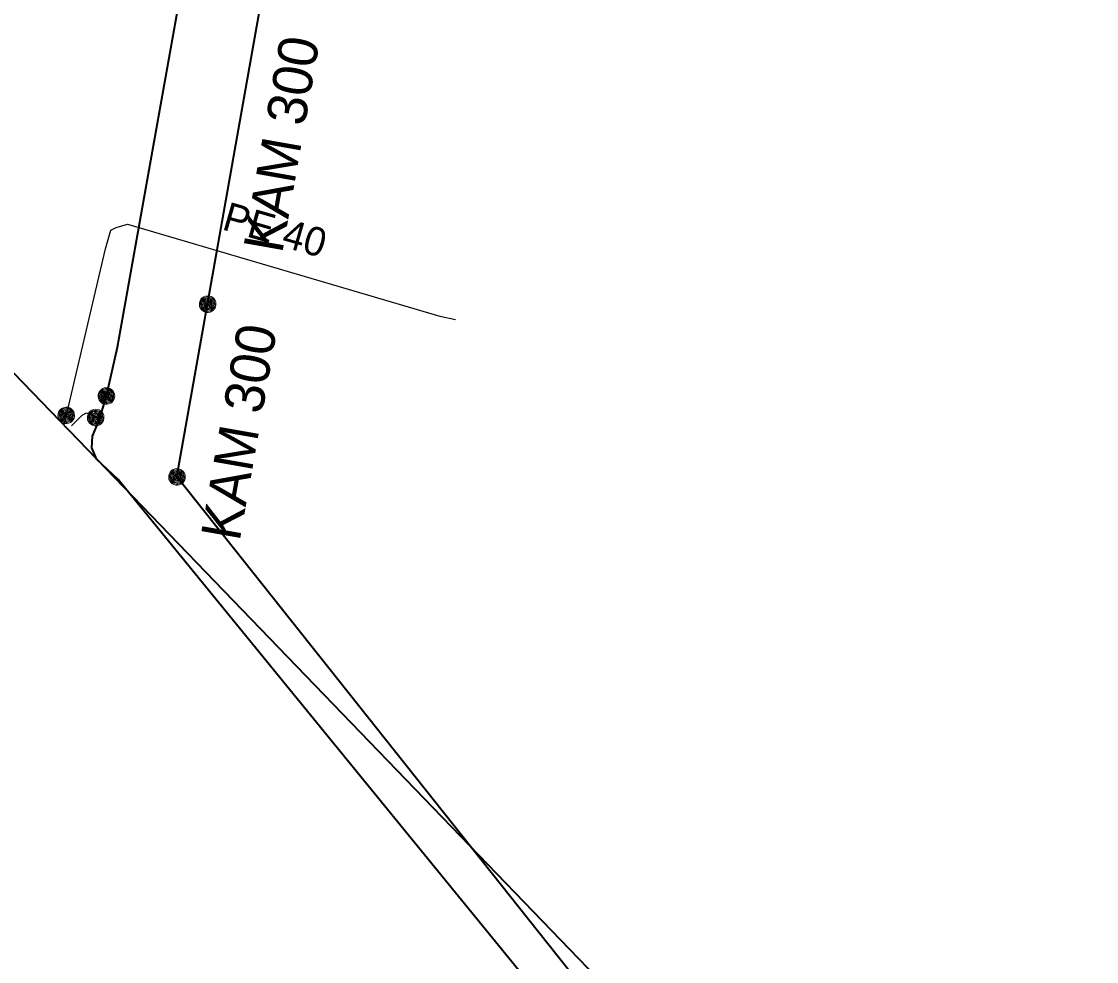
# Model space of a CAD drawing. Extents: x -867121 to -866743, y -1014362 to -1014088.
# Drawn here: x -866794.67 to -866764.7, y -1014270.01 to -1014243.81 of the extents above; entities that cross this region are included whole.
import ezdxf

# ---------------------------------------------------------------- set-up
doc = ezdxf.new("R2010")
doc.units = 0
doc.header["$LTSCALE"] = 0.44
for name, color, linetype, lineweight in [('1', 7, 'Continuous', 35), ('12', 7, 'Continuous', 13), ('21', 7, 'Continuous', 35), ('3', 7, 'Continuous', 25), ('32', 7, 'Continuous', 13)]:
    doc.layers.add(name, color=color, linetype=linetype, lineweight=lineweight)

msp = doc.modelspace()

# ---------------------------------------------------------------- linework, layer by layer
at = {"layer": '1'}
for p, q in [((-866764.699, -1014284.885), (-866792.574, -1014256.008)), ((-866765.275, -1014289.274), (-866791.98, -1014256.58))]:
    msp.add_line(p, q, dxfattribs=at)
for points in [[(-866791.979, -1014256.58), (-866792.57, -1014256.02), (-866792.709, -1014255.69), (-866792.69, -1014255.37), (-866792.5, -1014254.9), (-866792.3, -1014254.24), (-866792, -1014252.89), (-866783.03, -1014202.67), (-866778.1, -1014171.95), (-866772.02, -1014133.72), (-866768.851, -1014115.7)], [(-866792.574, -1014256.008), (-866841.087, -1014205.753), (-866857.467, -1014153.141), (-866859.393, -1014135.973), (-866869.502, -1014132.716), (-866897.758, -1014124.346), (-866897.929, -1014124.295)]]:
    msp.add_lwpolyline(points, dxfattribs=at)
at = {"layer": '12'}
for points in [[(-866792.076, -1014254.249), (-866792.082, -1014254.197), (-866792.099, -1014254.147), (-866792.128, -1014254.103), (-866792.165, -1014254.066), (-866792.21, -1014254.039), (-866792.26, -1014254.022), (-866792.313, -1014254.018), (-866792.365, -1014254.025), (-866792.414, -1014254.044), (-866792.457, -1014254.073), (-866792.493, -1014254.112), (-866792.519, -1014254.157), (-866792.535, -1014254.208), (-866792.538, -1014254.26), (-866792.53, -1014254.312), (-866792.51, -1014254.361), (-866792.479, -1014254.404), (-866792.44, -1014254.438), (-866792.394, -1014254.464), (-866792.343, -1014254.478), (-866792.29, -1014254.48), (-866792.239, -1014254.47), (-866792.191, -1014254.449), (-866792.148, -1014254.418), (-866792.114, -1014254.377), (-866792.09, -1014254.331), (-866792.078, -1014254.28)], [(-866792.106, -1014254.249), (-866792.112, -1014254.2), (-866792.129, -1014254.154), (-866792.157, -1014254.114), (-866792.194, -1014254.082), (-866792.238, -1014254.06), (-866792.286, -1014254.049), (-866792.335, -1014254.049), (-866792.382, -1014254.062), (-866792.425, -1014254.086), (-866792.461, -1014254.119), (-866792.488, -1014254.16), (-866792.504, -1014254.207), (-866792.508, -1014254.256), (-866792.501, -1014254.304), (-866792.482, -1014254.349), (-866792.452, -1014254.389), (-866792.414, -1014254.42), (-866792.37, -1014254.44), (-866792.322, -1014254.45), (-866792.273, -1014254.448), (-866792.226, -1014254.433), (-866792.183, -1014254.408), (-866792.149, -1014254.374), (-866792.123, -1014254.332), (-866792.109, -1014254.285)], [(-866792.136, -1014254.249), (-866792.142, -1014254.204), (-866792.159, -1014254.162), (-866792.187, -1014254.127), (-866792.223, -1014254.1), (-866792.265, -1014254.083), (-866792.31, -1014254.078), (-866792.355, -1014254.084), (-866792.396, -1014254.103), (-866792.431, -1014254.131), (-866792.458, -1014254.168), (-866792.474, -1014254.21), (-866792.478, -1014254.255), (-866792.471, -1014254.3), (-866792.452, -1014254.341), (-866792.423, -1014254.375), (-866792.386, -1014254.401), (-866792.343, -1014254.417), (-866792.298, -1014254.42), (-866792.253, -1014254.412), (-866792.213, -1014254.392), (-866792.179, -1014254.363), (-866792.153, -1014254.325), (-866792.139, -1014254.282)], [(-866792.166, -1014254.249), (-866792.171, -1014254.208), (-866792.189, -1014254.171), (-866792.216, -1014254.14), (-866792.251, -1014254.119), (-866792.291, -1014254.108), (-866792.332, -1014254.11), (-866792.371, -1014254.123), (-866792.405, -1014254.147), (-866792.43, -1014254.179), (-866792.445, -1014254.217), (-866792.448, -1014254.258), (-866792.44, -1014254.298), (-866792.42, -1014254.334), (-866792.391, -1014254.363), (-866792.354, -1014254.382), (-866792.314, -1014254.39), (-866792.273, -1014254.386), (-866792.235, -1014254.371), (-866792.203, -1014254.345), (-866792.18, -1014254.311), (-866792.167, -1014254.272)], [(-866792.196, -1014254.249), (-866792.201, -1014254.213), (-866792.219, -1014254.181), (-866792.245, -1014254.156), (-866792.279, -1014254.141), (-866792.315, -1014254.138), (-866792.35, -1014254.146), (-866792.381, -1014254.166), (-866792.404, -1014254.194), (-866792.417, -1014254.228), (-866792.417, -1014254.265), (-866792.406, -1014254.3), (-866792.385, -1014254.329), (-866792.355, -1014254.35), (-866792.32, -1014254.36), (-866792.283, -1014254.358), (-866792.249, -1014254.344), (-866792.222, -1014254.321), (-866792.203, -1014254.289), (-866792.196, -1014254.254)], [(-866792.226, -1014254.249), (-866792.231, -1014254.218), (-866792.248, -1014254.192), (-866792.274, -1014254.175), (-866792.304, -1014254.168), (-866792.335, -1014254.172), (-866792.362, -1014254.189), (-866792.38, -1014254.213), (-866792.388, -1014254.244), (-866792.384, -1014254.274), (-866792.369, -1014254.302), (-866792.345, -1014254.321), (-866792.315, -1014254.33), (-866792.284, -1014254.327), (-866792.256, -1014254.313), (-866792.236, -1014254.289), (-866792.226, -1014254.26)], [(-866792.256, -1014254.249), (-866792.261, -1014254.225), (-866792.278, -1014254.207), (-866792.301, -1014254.198), (-866792.325, -1014254.201), (-866792.346, -1014254.215), (-866792.357, -1014254.237), (-866792.357, -1014254.262), (-866792.345, -1014254.283), (-866792.325, -1014254.297), (-866792.3, -1014254.3), (-866792.277, -1014254.291), (-866792.261, -1014254.273)], [(-866792.286, -1014254.249), (-866792.291, -1014254.234), (-866792.306, -1014254.228), (-866792.321, -1014254.232), (-866792.328, -1014254.246), (-866792.324, -1014254.261), (-866792.311, -1014254.27), (-866792.296, -1014254.267), (-866792.286, -1014254.255)], [(-866793.196, -1014254.789), (-866793.202, -1014254.737), (-866793.219, -1014254.687), (-866793.248, -1014254.643), (-866793.285, -1014254.606), (-866793.33, -1014254.579), (-866793.38, -1014254.562), (-866793.433, -1014254.558), (-866793.485, -1014254.565), (-866793.534, -1014254.584), (-866793.577, -1014254.613), (-866793.613, -1014254.652), (-866793.639, -1014254.697), (-866793.655, -1014254.748), (-866793.658, -1014254.8), (-866793.65, -1014254.852), (-866793.63, -1014254.901), (-866793.599, -1014254.944), (-866793.56, -1014254.978), (-866793.514, -1014255.004), (-866793.463, -1014255.018), (-866793.41, -1014255.02), (-866793.359, -1014255.01), (-866793.311, -1014254.989), (-866793.268, -1014254.958), (-866793.234, -1014254.917), (-866793.21, -1014254.871), (-866793.198, -1014254.82)], [(-866793.226, -1014254.789), (-866793.232, -1014254.74), (-866793.249, -1014254.694), (-866793.277, -1014254.654), (-866793.314, -1014254.622), (-866793.358, -1014254.6), (-866793.406, -1014254.589), (-866793.455, -1014254.589), (-866793.502, -1014254.602), (-866793.545, -1014254.626), (-866793.581, -1014254.659), (-866793.608, -1014254.7), (-866793.624, -1014254.747), (-866793.628, -1014254.796), (-866793.621, -1014254.844), (-866793.602, -1014254.889), (-866793.572, -1014254.929), (-866793.534, -1014254.96), (-866793.49, -1014254.98), (-866793.442, -1014254.99), (-866793.393, -1014254.988), (-866793.346, -1014254.973), (-866793.303, -1014254.948), (-866793.269, -1014254.914), (-866793.243, -1014254.872), (-866793.229, -1014254.825)], [(-866793.256, -1014254.789), (-866793.262, -1014254.744), (-866793.279, -1014254.702), (-866793.307, -1014254.667), (-866793.343, -1014254.64), (-866793.385, -1014254.623), (-866793.43, -1014254.618), (-866793.475, -1014254.624), (-866793.516, -1014254.643), (-866793.551, -1014254.671), (-866793.578, -1014254.708), (-866793.594, -1014254.75), (-866793.598, -1014254.795), (-866793.591, -1014254.84), (-866793.572, -1014254.881), (-866793.543, -1014254.915), (-866793.506, -1014254.941), (-866793.463, -1014254.957), (-866793.418, -1014254.96), (-866793.373, -1014254.952), (-866793.333, -1014254.932), (-866793.299, -1014254.903), (-866793.273, -1014254.865), (-866793.259, -1014254.822)], [(-866793.286, -1014254.789), (-866793.291, -1014254.748), (-866793.309, -1014254.711), (-866793.336, -1014254.68), (-866793.371, -1014254.659), (-866793.411, -1014254.648), (-866793.452, -1014254.65), (-866793.491, -1014254.663), (-866793.525, -1014254.687), (-866793.55, -1014254.719), (-866793.565, -1014254.757), (-866793.568, -1014254.798), (-866793.56, -1014254.838), (-866793.54, -1014254.874), (-866793.511, -1014254.903), (-866793.474, -1014254.922), (-866793.434, -1014254.93), (-866793.393, -1014254.926), (-866793.355, -1014254.911), (-866793.323, -1014254.885), (-866793.3, -1014254.851), (-866793.287, -1014254.812)], [(-866792.375, -1014254.849), (-866792.382, -1014254.797), (-866792.399, -1014254.747), (-866792.428, -1014254.703), (-866792.465, -1014254.666), (-866792.51, -1014254.639), (-866792.559, -1014254.622), (-866792.613, -1014254.618), (-866792.664, -1014254.625), (-866792.713, -1014254.644), (-866792.757, -1014254.673), (-866792.793, -1014254.712), (-866792.819, -1014254.757), (-866792.835, -1014254.808), (-866792.838, -1014254.86), (-866792.83, -1014254.912), (-866792.809, -1014254.961), (-866792.779, -1014255.004), (-866792.74, -1014255.038), (-866792.694, -1014255.064), (-866792.642, -1014255.078), (-866792.59, -1014255.08), (-866792.539, -1014255.07), (-866792.49, -1014255.049), (-866792.448, -1014255.018), (-866792.414, -1014254.977), (-866792.39, -1014254.931), (-866792.377, -1014254.88)], [(-866792.406, -1014254.849), (-866792.412, -1014254.8), (-866792.429, -1014254.754), (-866792.456, -1014254.714), (-866792.494, -1014254.682), (-866792.538, -1014254.66), (-866792.586, -1014254.649), (-866792.635, -1014254.649), (-866792.681, -1014254.662), (-866792.725, -1014254.686), (-866792.761, -1014254.719), (-866792.788, -1014254.76), (-866792.804, -1014254.807), (-866792.808, -1014254.856), (-866792.801, -1014254.904), (-866792.782, -1014254.949), (-866792.752, -1014254.989), (-866792.713, -1014255.02), (-866792.669, -1014255.04), (-866792.622, -1014255.05), (-866792.573, -1014255.048), (-866792.526, -1014255.033), (-866792.483, -1014255.008), (-866792.448, -1014254.974), (-866792.423, -1014254.932), (-866792.409, -1014254.885)], [(-866793.316, -1014254.789), (-866793.321, -1014254.753), (-866793.339, -1014254.721), (-866793.365, -1014254.696), (-866793.399, -1014254.681), (-866793.435, -1014254.678), (-866793.47, -1014254.686), (-866793.501, -1014254.706), (-866793.524, -1014254.734), (-866793.537, -1014254.768), (-866793.537, -1014254.805), (-866793.526, -1014254.84), (-866793.505, -1014254.869), (-866793.475, -1014254.89), (-866793.44, -1014254.9), (-866793.403, -1014254.898), (-866793.369, -1014254.884), (-866793.342, -1014254.861), (-866793.323, -1014254.829), (-866793.316, -1014254.794)], [(-866793.346, -1014254.789), (-866793.351, -1014254.758), (-866793.368, -1014254.732), (-866793.394, -1014254.715), (-866793.424, -1014254.708), (-866793.455, -1014254.712), (-866793.482, -1014254.729), (-866793.5, -1014254.753), (-866793.508, -1014254.784), (-866793.504, -1014254.814), (-866793.489, -1014254.842), (-866793.465, -1014254.861), (-866793.435, -1014254.87), (-866793.404, -1014254.867), (-866793.376, -1014254.853), (-866793.356, -1014254.829), (-866793.346, -1014254.8)], [(-866793.376, -1014254.789), (-866793.381, -1014254.765), (-866793.398, -1014254.747), (-866793.421, -1014254.738), (-866793.445, -1014254.741), (-866793.466, -1014254.755), (-866793.477, -1014254.777), (-866793.477, -1014254.802), (-866793.465, -1014254.823), (-866793.445, -1014254.837), (-866793.42, -1014254.84), (-866793.397, -1014254.831), (-866793.381, -1014254.813)], [(-866793.406, -1014254.789), (-866793.411, -1014254.774), (-866793.426, -1014254.768), (-866793.441, -1014254.772), (-866793.448, -1014254.786), (-866793.444, -1014254.801), (-866793.431, -1014254.81), (-866793.416, -1014254.807), (-866793.406, -1014254.795)], [(-866792.436, -1014254.849), (-866792.441, -1014254.804), (-866792.458, -1014254.762), (-866792.487, -1014254.727), (-866792.522, -1014254.7), (-866792.565, -1014254.683), (-866792.61, -1014254.678), (-866792.654, -1014254.684), (-866792.696, -1014254.703), (-866792.73, -1014254.731), (-866792.757, -1014254.768), (-866792.774, -1014254.81), (-866792.777, -1014254.855), (-866792.771, -1014254.9), (-866792.752, -1014254.941), (-866792.723, -1014254.975), (-866792.686, -1014255.001), (-866792.642, -1014255.017), (-866792.598, -1014255.02), (-866792.553, -1014255.012), (-866792.512, -1014254.992), (-866792.478, -1014254.963), (-866792.453, -1014254.925), (-866792.439, -1014254.882)], [(-866792.466, -1014254.849), (-866792.47, -1014254.808), (-866792.489, -1014254.771), (-866792.516, -1014254.74), (-866792.551, -1014254.719), (-866792.591, -1014254.708), (-866792.632, -1014254.71), (-866792.671, -1014254.723), (-866792.705, -1014254.747), (-866792.73, -1014254.779), (-866792.745, -1014254.817), (-866792.747, -1014254.858), (-866792.74, -1014254.898), (-866792.72, -1014254.934), (-866792.691, -1014254.963), (-866792.654, -1014254.982), (-866792.614, -1014254.99), (-866792.573, -1014254.986), (-866792.534, -1014254.971), (-866792.502, -1014254.945), (-866792.48, -1014254.911), (-866792.467, -1014254.872)], [(-866792.495, -1014254.849), (-866792.5, -1014254.813), (-866792.519, -1014254.781), (-866792.544, -1014254.756), (-866792.578, -1014254.741), (-866792.615, -1014254.738), (-866792.649, -1014254.746), (-866792.681, -1014254.766), (-866792.703, -1014254.794), (-866792.717, -1014254.828), (-866792.717, -1014254.865), (-866792.706, -1014254.9), (-866792.684, -1014254.929), (-866792.654, -1014254.95), (-866792.62, -1014254.96), (-866792.583, -1014254.958), (-866792.549, -1014254.944), (-866792.522, -1014254.921), (-866792.502, -1014254.889), (-866792.495, -1014254.854)], [(-866792.526, -1014254.849), (-866792.531, -1014254.818), (-866792.548, -1014254.792), (-866792.573, -1014254.775), (-866792.603, -1014254.768), (-866792.635, -1014254.772), (-866792.662, -1014254.789), (-866792.679, -1014254.813), (-866792.688, -1014254.844), (-866792.684, -1014254.874), (-866792.669, -1014254.902), (-866792.644, -1014254.921), (-866792.615, -1014254.93), (-866792.583, -1014254.927), (-866792.556, -1014254.913), (-866792.536, -1014254.889), (-866792.526, -1014254.86)], [(-866792.556, -1014254.849), (-866792.561, -1014254.825), (-866792.578, -1014254.807), (-866792.6, -1014254.798), (-866792.625, -1014254.801), (-866792.646, -1014254.815), (-866792.657, -1014254.837), (-866792.657, -1014254.862), (-866792.644, -1014254.883), (-866792.625, -1014254.897), (-866792.6, -1014254.9), (-866792.576, -1014254.891), (-866792.561, -1014254.873)], [(-866792.586, -1014254.849), (-866792.591, -1014254.834), (-866792.605, -1014254.828), (-866792.62, -1014254.832), (-866792.627, -1014254.846), (-866792.624, -1014254.861), (-866792.61, -1014254.87), (-866792.595, -1014254.867), (-866792.586, -1014254.855)]]:
    msp.add_lwpolyline(points, close=True, dxfattribs=at)
at = {"layer": '21'}
for p, q in [((-866789.484, -1014251.689), (-866787.796, -1014242.174)), ((-866790.339, -1014256.505), (-866789.484, -1014251.689))]:
    msp.add_line(p, q, dxfattribs=at)
msp.add_lwpolyline([(-866765.121, -1014288.097), (-866766.707, -1014286.245), (-866790.339, -1014256.505)], dxfattribs=at)
at = {"layer": '3'}
for points in [[(-866793.495, -1014255.054), (-866793.42, -1014254.78), (-866792.33, -1014250.15), (-866792.18, -1014249.63), (-866792.03, -1014249.55), (-866791.72, -1014249.46), (-866783.01, -1014252.02), (-866782.571, -1014252.12)], [(-866793.28, -1014255.08), (-866792.98, -1014254.78), (-866792.86, -1014254.72), (-866792.599, -1014254.84), (-866792.5, -1014254.9)]]:
    msp.add_lwpolyline(points, dxfattribs=at)
at = {"layer": '32'}
for points in [[(-866789.253, -1014251.689), (-866789.259, -1014251.637), (-866789.276, -1014251.587), (-866789.305, -1014251.543), (-866789.342, -1014251.506), (-866789.387, -1014251.479), (-866789.437, -1014251.462), (-866789.49, -1014251.458), (-866789.542, -1014251.465), (-866789.591, -1014251.484), (-866789.634, -1014251.513), (-866789.67, -1014251.552), (-866789.696, -1014251.597), (-866789.712, -1014251.648), (-866789.715, -1014251.7), (-866789.707, -1014251.752), (-866789.687, -1014251.801), (-866789.656, -1014251.844), (-866789.617, -1014251.878), (-866789.571, -1014251.904), (-866789.52, -1014251.918), (-866789.467, -1014251.92), (-866789.416, -1014251.91), (-866789.368, -1014251.889), (-866789.325, -1014251.858), (-866789.291, -1014251.817), (-866789.267, -1014251.771), (-866789.255, -1014251.72)], [(-866789.283, -1014251.689), (-866789.289, -1014251.64), (-866789.306, -1014251.594), (-866789.334, -1014251.554), (-866789.371, -1014251.522), (-866789.415, -1014251.5), (-866789.463, -1014251.489), (-866789.512, -1014251.489), (-866789.559, -1014251.502), (-866789.602, -1014251.526), (-866789.638, -1014251.559), (-866789.665, -1014251.6), (-866789.681, -1014251.647), (-866789.685, -1014251.696), (-866789.678, -1014251.744), (-866789.659, -1014251.789), (-866789.629, -1014251.829), (-866789.591, -1014251.86), (-866789.547, -1014251.88), (-866789.499, -1014251.89), (-866789.45, -1014251.888), (-866789.403, -1014251.873), (-866789.36, -1014251.848), (-866789.326, -1014251.814), (-866789.3, -1014251.772), (-866789.286, -1014251.725)], [(-866789.313, -1014251.689), (-866789.319, -1014251.644), (-866789.336, -1014251.602), (-866789.364, -1014251.567), (-866789.4, -1014251.54), (-866789.442, -1014251.523), (-866789.487, -1014251.518), (-866789.532, -1014251.524), (-866789.573, -1014251.543), (-866789.608, -1014251.571), (-866789.635, -1014251.608), (-866789.651, -1014251.65), (-866789.655, -1014251.695), (-866789.648, -1014251.74), (-866789.629, -1014251.781), (-866789.6, -1014251.815), (-866789.563, -1014251.841), (-866789.52, -1014251.857), (-866789.475, -1014251.86), (-866789.43, -1014251.852), (-866789.39, -1014251.832), (-866789.356, -1014251.803), (-866789.33, -1014251.765), (-866789.316, -1014251.722)], [(-866789.343, -1014251.689), (-866789.348, -1014251.648), (-866789.366, -1014251.611), (-866789.393, -1014251.58), (-866789.428, -1014251.559), (-866789.468, -1014251.548), (-866789.509, -1014251.55), (-866789.548, -1014251.563), (-866789.582, -1014251.587), (-866789.607, -1014251.619), (-866789.622, -1014251.657), (-866789.625, -1014251.698), (-866789.617, -1014251.738), (-866789.597, -1014251.774), (-866789.568, -1014251.803), (-866789.531, -1014251.822), (-866789.491, -1014251.83), (-866789.45, -1014251.826), (-866789.412, -1014251.811), (-866789.38, -1014251.785), (-866789.357, -1014251.751), (-866789.344, -1014251.712)], [(-866789.373, -1014251.689), (-866789.378, -1014251.653), (-866789.396, -1014251.621), (-866789.422, -1014251.596), (-866789.456, -1014251.581), (-866789.492, -1014251.578), (-866789.527, -1014251.586), (-866789.558, -1014251.606), (-866789.581, -1014251.634), (-866789.594, -1014251.668), (-866789.594, -1014251.705), (-866789.583, -1014251.74), (-866789.562, -1014251.769), (-866789.532, -1014251.79), (-866789.497, -1014251.8), (-866789.46, -1014251.798), (-866789.426, -1014251.784), (-866789.399, -1014251.761), (-866789.38, -1014251.729), (-866789.373, -1014251.694)], [(-866789.403, -1014251.689), (-866789.408, -1014251.658), (-866789.425, -1014251.632), (-866789.451, -1014251.615), (-866789.481, -1014251.608), (-866789.512, -1014251.612), (-866789.539, -1014251.629), (-866789.557, -1014251.653), (-866789.565, -1014251.684), (-866789.561, -1014251.714), (-866789.546, -1014251.742), (-866789.522, -1014251.761), (-866789.492, -1014251.77), (-866789.461, -1014251.767), (-866789.433, -1014251.753), (-866789.413, -1014251.729), (-866789.403, -1014251.7)], [(-866789.433, -1014251.689), (-866789.438, -1014251.665), (-866789.455, -1014251.647), (-866789.478, -1014251.638), (-866789.502, -1014251.641), (-866789.523, -1014251.655), (-866789.534, -1014251.677), (-866789.534, -1014251.702), (-866789.522, -1014251.723), (-866789.502, -1014251.737), (-866789.477, -1014251.74), (-866789.454, -1014251.731), (-866789.438, -1014251.713)], [(-866789.463, -1014251.689), (-866789.468, -1014251.674), (-866789.483, -1014251.668), (-866789.498, -1014251.672), (-866789.505, -1014251.686), (-866789.501, -1014251.701), (-866789.488, -1014251.71), (-866789.473, -1014251.707), (-866789.463, -1014251.695)], [(-866790.108, -1014256.505), (-866790.114, -1014256.453), (-866790.131, -1014256.403), (-866790.16, -1014256.359), (-866790.197, -1014256.322), (-866790.242, -1014256.295), (-866790.292, -1014256.278), (-866790.345, -1014256.274), (-866790.397, -1014256.281), (-866790.446, -1014256.3), (-866790.489, -1014256.329), (-866790.525, -1014256.368), (-866790.551, -1014256.413), (-866790.567, -1014256.464), (-866790.57, -1014256.516), (-866790.562, -1014256.568), (-866790.542, -1014256.617), (-866790.511, -1014256.66), (-866790.472, -1014256.694), (-866790.426, -1014256.72), (-866790.375, -1014256.734), (-866790.322, -1014256.736), (-866790.271, -1014256.726), (-866790.223, -1014256.705), (-866790.18, -1014256.674), (-866790.146, -1014256.633), (-866790.122, -1014256.587), (-866790.11, -1014256.536)], [(-866790.138, -1014256.505), (-866790.144, -1014256.456), (-866790.161, -1014256.41), (-866790.189, -1014256.37), (-866790.226, -1014256.338), (-866790.27, -1014256.316), (-866790.318, -1014256.305), (-866790.367, -1014256.305), (-866790.414, -1014256.318), (-866790.457, -1014256.342), (-866790.493, -1014256.375), (-866790.52, -1014256.416), (-866790.536, -1014256.463), (-866790.54, -1014256.512), (-866790.533, -1014256.56), (-866790.514, -1014256.605), (-866790.484, -1014256.645), (-866790.446, -1014256.676), (-866790.402, -1014256.696), (-866790.354, -1014256.706), (-866790.305, -1014256.704), (-866790.258, -1014256.689), (-866790.215, -1014256.664), (-866790.181, -1014256.63), (-866790.155, -1014256.588), (-866790.141, -1014256.541)], [(-866790.168, -1014256.505), (-866790.174, -1014256.46), (-866790.191, -1014256.418), (-866790.219, -1014256.383), (-866790.255, -1014256.356), (-866790.297, -1014256.339), (-866790.342, -1014256.334), (-866790.387, -1014256.34), (-866790.428, -1014256.359), (-866790.463, -1014256.387), (-866790.49, -1014256.424), (-866790.506, -1014256.466), (-866790.51, -1014256.511), (-866790.503, -1014256.556), (-866790.484, -1014256.597), (-866790.455, -1014256.631), (-866790.418, -1014256.657), (-866790.375, -1014256.673), (-866790.33, -1014256.676), (-866790.285, -1014256.668), (-866790.245, -1014256.648), (-866790.211, -1014256.619), (-866790.185, -1014256.581), (-866790.171, -1014256.538)], [(-866790.198, -1014256.505), (-866790.203, -1014256.464), (-866790.221, -1014256.427), (-866790.248, -1014256.396), (-866790.283, -1014256.375), (-866790.323, -1014256.364), (-866790.364, -1014256.366), (-866790.403, -1014256.379), (-866790.437, -1014256.403), (-866790.462, -1014256.435), (-866790.477, -1014256.473), (-866790.48, -1014256.514), (-866790.472, -1014256.554), (-866790.452, -1014256.59), (-866790.423, -1014256.619), (-866790.386, -1014256.638), (-866790.346, -1014256.646), (-866790.305, -1014256.642), (-866790.267, -1014256.627), (-866790.235, -1014256.601), (-866790.212, -1014256.567), (-866790.199, -1014256.528)], [(-866790.228, -1014256.505), (-866790.233, -1014256.469), (-866790.251, -1014256.437), (-866790.277, -1014256.412), (-866790.311, -1014256.397), (-866790.347, -1014256.394), (-866790.382, -1014256.402), (-866790.413, -1014256.422), (-866790.436, -1014256.45), (-866790.449, -1014256.484), (-866790.449, -1014256.521), (-866790.438, -1014256.556), (-866790.417, -1014256.585), (-866790.387, -1014256.606), (-866790.352, -1014256.616), (-866790.315, -1014256.614), (-866790.281, -1014256.6), (-866790.254, -1014256.577), (-866790.235, -1014256.545), (-866790.228, -1014256.51)], [(-866790.258, -1014256.505), (-866790.263, -1014256.474), (-866790.28, -1014256.448), (-866790.306, -1014256.431), (-866790.336, -1014256.424), (-866790.367, -1014256.428), (-866790.394, -1014256.445), (-866790.412, -1014256.469), (-866790.42, -1014256.5), (-866790.416, -1014256.53), (-866790.401, -1014256.558), (-866790.377, -1014256.577), (-866790.347, -1014256.586), (-866790.316, -1014256.583), (-866790.288, -1014256.569), (-866790.268, -1014256.545), (-866790.258, -1014256.516)], [(-866790.288, -1014256.505), (-866790.293, -1014256.481), (-866790.31, -1014256.463), (-866790.333, -1014256.454), (-866790.357, -1014256.457), (-866790.378, -1014256.471), (-866790.389, -1014256.493), (-866790.389, -1014256.518), (-866790.377, -1014256.539), (-866790.357, -1014256.553), (-866790.332, -1014256.556), (-866790.309, -1014256.547), (-866790.293, -1014256.529)], [(-866790.318, -1014256.505), (-866790.323, -1014256.49), (-866790.338, -1014256.484), (-866790.353, -1014256.488), (-866790.36, -1014256.502), (-866790.356, -1014256.517), (-866790.343, -1014256.526), (-866790.328, -1014256.523), (-866790.318, -1014256.511)]]:
    msp.add_lwpolyline(points, close=True, dxfattribs=at)

# ---------------------------------------------------------------- texts
at = {"layer": '1'}
for s, height, rotation, p in [('KAM 300 ', 1.1, 80, (-866787.408, -1014250.299)), ('PE 40 ', 0.8, 344, (-866789.114, -1014249.599)), ('KAM 300 ', 1.1, 80, (-866788.595, -1014258.324))]:
    msp.add_text(s, height=height, rotation=rotation, dxfattribs=at).set_placement(p)

doc.saveas('drawing.dxf')
